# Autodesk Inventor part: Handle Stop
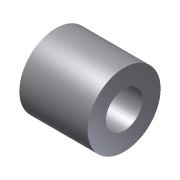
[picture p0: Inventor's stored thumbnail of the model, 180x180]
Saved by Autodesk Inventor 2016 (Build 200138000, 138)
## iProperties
Shininess: 77.0
Length Units: 11269
Angle Units: 11279
Time Units: 11290
Mass Units: 11283
Length Display Precision: 3
Angle Display Precision: 2
Compacted: True
Created: 2002-02
Part Number: Handle Stop
Document SubType Name: Modeling
Designer: ***
Density: 1 g/cm^3
Material: Generic
Mass: 2.36248 g
Surface Area: 14.8283 cm^2
Volume: 2.36248 cm^3
Appearance: Default
Density: 0.0
Volumn: 0.0
Area: 0.0
PropertySet Name: Model Information
Control State: 0
Master: False
Checked Out: False
Author: ***
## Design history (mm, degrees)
sketch "Sketch1"
  geometry: L1 (0, 0)-(0, -2); L2 (0, -2)-(8, -2); L3 (8, -2)-(8, 13); L4 (8, 13)-(4, 13); L5 (4, 13)-(4, 0); L6 (4, 0)-(0, 0)
  constraints: 12 end point, 4 parallel, 1 perpendicular, 1 vertical
  dimensions: "d0" = 16 diameter of L3 L1; "d1" = 8 diameter of L5 L1; "d2" = 2 distance of L1.start L1.end; "d3" = 15 distance of L2.end L3.end
revolve "Revolution1" sketch "Sketch1" stored, may be unused: angle "d4" = 90 deg
body "Solid1"
